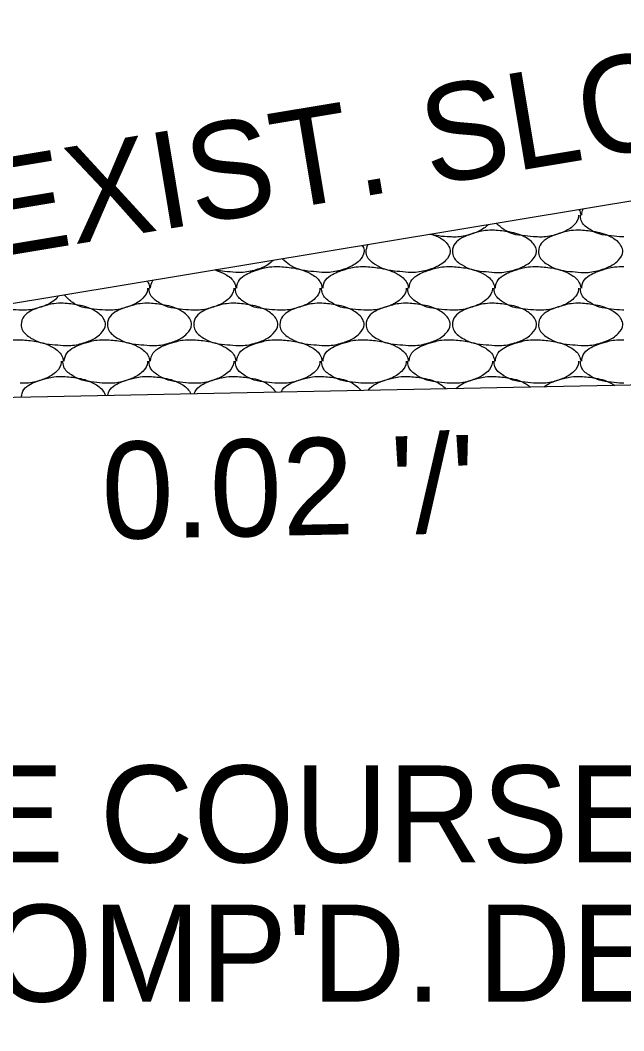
# Model space of a CAD drawing. Extents: x 1364961 to 1365294, y 367927 to 368034.
# Drawn here: x 1365179.35 to 1365182.93, y 367966.75 to 367972.75 of the extents above; entities that cross this region are included whole.
import ezdxf

# ---------------------------------------------------------------- set-up
doc = ezdxf.new("R2010")
doc.units = 0
doc.layers.add('Default', color=7, linetype='Continuous')

msp = doc.modelspace()

# ---------------------------------------------------------------- linework, layer by layer
at = {"layer": 'Default'}
for p, q in [((1365187.4981, 367972.4254), (1365166.1432, 367968.8787)), ((1365180.8861, 367971.2854), (1365180.8921, 367971.2854)), ((1365181.3981, 367971.2854), (1365181.4041, 367971.2854)), ((1365181.9101, 367971.2854), (1365181.9161, 367971.2854)), ((1365182.4221, 367971.2854), (1365182.4281, 367971.2854)), ((1365179.3501, 367970.8514), (1365179.3561, 367970.8514)), ((1365179.8621, 367970.8514), (1365179.8681, 367970.8514)), ((1365180.3741, 367970.8514), (1365180.3801, 367970.8514)), ((1365180.8861, 367970.8514), (1365180.8921, 367970.8514)), ((1365181.3981, 367970.8514), (1365181.4041, 367970.8514)), ((1365181.9101, 367970.8514), (1365181.9161, 367970.8514)), ((1365182.4221, 367970.8514), (1365182.4281, 367970.8514)), ((1365193.4821, 367970.7914), (1365175.4981, 367970.4324))]:
    msp.add_line(p, q, dxfattribs=at)
for points in [[(1365182.6701, 367971.6234), (1365182.6781, 367971.5934), (1365182.6781, 367971.5914)], [(1365182.6841, 367971.5914), (1365182.6841, 367971.5934), (1365182.6921, 367971.6274)], [(1365182.6661, 367971.5914), (1365182.6661, 367971.5854), (1365182.6381, 367971.5314), (1365182.6081, 367971.5074), (1365182.5461, 367971.4794), (1365182.4601, 367971.4614), (1365182.4221, 367971.4614)], [(1365182.9341, 367971.4614), (1365182.9261, 367971.4614), (1365182.8601, 367971.4674), (1365182.7881, 367971.4794), (1365182.7341, 367971.5054), (1365182.6841, 367971.5514), (1365182.6761, 367971.5854), (1365182.6761, 367971.5914)], [(1365182.1281, 367971.5334), (1365182.1261, 367971.5314), (1365182.0961, 367971.5074), (1365182.0341, 367971.4794), (1365181.9481, 367971.4614), (1365181.9101, 367971.4614)], [(1365182.1661, 367971.5014), (1365182.2541, 367971.4914), (1365182.3561, 367971.4554), (1365182.4081, 367971.4054), (1365182.4161, 367971.3754), (1365182.3881, 367971.3214), (1365182.3581, 367971.2974), (1365182.2961, 367971.2694), (1365182.2101, 367971.2514), (1365182.1661, 367971.2514), (1365182.1001, 367971.2574), (1365182.0281, 367971.2694), (1365181.9741, 367971.2954), (1365181.9241, 367971.3414), (1365181.9161, 367971.3754), (1365181.9321, 367971.4234), (1365181.9721, 367971.4554), (1365182.0121, 367971.4734), (1365182.0721, 367971.4914), (1365182.1101, 367971.4994), (1365182.1661, 367971.5014)], [(1365182.4221, 367971.4614), (1365182.4141, 367971.4614), (1365182.3481, 367971.4674), (1365182.2761, 367971.4794), (1365182.2221, 367971.5054), (1365182.1781, 367971.5414)], [(1365182.6781, 367971.5014), (1365182.7661, 367971.4914), (1365182.8681, 367971.4554), (1365182.9201, 367971.4054), (1365182.9281, 367971.3754), (1365182.9001, 367971.3214), (1365182.8701, 367971.2974), (1365182.8081, 367971.2694), (1365182.7221, 367971.2514), (1365182.6781, 367971.2514), (1365182.6121, 367971.2574), (1365182.5401, 367971.2694), (1365182.4861, 367971.2954), (1365182.4361, 367971.3414), (1365182.4281, 367971.3754), (1365182.4441, 367971.4234), (1365182.4841, 367971.4554), (1365182.5241, 367971.4734), (1365182.5841, 367971.4914), (1365182.6221, 367971.4994), (1365182.6781, 367971.5014)], [(1365181.7931, 367971.4774), (1365181.8441, 367971.4554), (1365181.8961, 367971.4054), (1365181.9041, 367971.3754), (1365181.8761, 367971.3214), (1365181.8461, 367971.2974), (1365181.7841, 367971.2694), (1365181.6981, 367971.2514), (1365181.6541, 367971.2514), (1365181.5881, 367971.2574), (1365181.5161, 367971.2694), (1365181.4621, 367971.2954), (1365181.4121, 367971.3414), (1365181.4041, 367971.3754), (1365181.4151, 367971.4154)], [(1365181.9101, 367971.4614), (1365181.9021, 367971.4614), (1365181.8361, 367971.4674), (1365181.7811, 367971.4754)], [(1365181.3811, 367971.4094), (1365181.3841, 367971.4054), (1365181.3921, 367971.3754), (1365181.3641, 367971.3214), (1365181.3341, 367971.2974), (1365181.2721, 367971.2694), (1365181.1861, 367971.2514), (1365181.1421, 367971.2514), (1365181.0761, 367971.2574), (1365181.0041, 367971.2694), (1365180.9501, 367971.2954), (1365180.9081, 367971.3304)], [(1365180.8521, 367971.3214), (1365180.8221, 367971.2974), (1365180.7601, 367971.2694), (1365180.6741, 367971.2514), (1365180.6301, 367971.2514), (1365180.5641, 367971.2574), (1365180.5121, 367971.2654)], [(1365180.5101, 367971.2644), (1365180.5701, 367971.2394), (1365180.6221, 367971.1894), (1365180.6301, 367971.1594), (1365180.6301, 367971.1574)], [(1365180.6361, 367971.1574), (1365180.6361, 367971.1594), (1365180.6521, 367971.2074), (1365180.6921, 367971.2394), (1365180.7321, 367971.2574), (1365180.7921, 367971.2754), (1365180.8301, 367971.2834), (1365180.8861, 367971.2854)], [(1365180.8921, 367971.2854), (1365180.9801, 367971.2754), (1365181.0821, 367971.2394), (1365181.1341, 367971.1894), (1365181.1421, 367971.1594), (1365181.1421, 367971.1574)], [(1365181.1481, 367971.1574), (1365181.1481, 367971.1594), (1365181.1641, 367971.2074), (1365181.2041, 367971.2394), (1365181.2441, 367971.2574), (1365181.3041, 367971.2754), (1365181.3421, 367971.2834), (1365181.3981, 367971.2854)], [(1365181.4041, 367971.2854), (1365181.4921, 367971.2754), (1365181.5941, 367971.2394), (1365181.6461, 367971.1894), (1365181.6541, 367971.1594), (1365181.6541, 367971.1574)], [(1365181.6601, 367971.1574), (1365181.6601, 367971.1594), (1365181.6761, 367971.2074), (1365181.7161, 367971.2394), (1365181.7561, 367971.2574), (1365181.8161, 367971.2754), (1365181.8541, 367971.2834), (1365181.9101, 367971.2854)], [(1365181.9161, 367971.2854), (1365182.0041, 367971.2754), (1365182.1061, 367971.2394), (1365182.1581, 367971.1894), (1365182.1661, 367971.1594), (1365182.1661, 367971.1574)], [(1365182.1721, 367971.1574), (1365182.1721, 367971.1594), (1365182.1881, 367971.2074), (1365182.2281, 367971.2394), (1365182.2681, 367971.2574), (1365182.3281, 367971.2754), (1365182.3661, 367971.2834), (1365182.4221, 367971.2854)], [(1365182.4281, 367971.2854), (1365182.5161, 367971.2754), (1365182.6181, 367971.2394), (1365182.6701, 367971.1894), (1365182.6781, 367971.1594), (1365182.6781, 367971.1574)], [(1365182.6841, 367971.1574), (1365182.6841, 367971.1594), (1365182.7001, 367971.2074), (1365182.7401, 367971.2394), (1365182.7801, 367971.2574), (1365182.8401, 367971.2754), (1365182.8781, 367971.2834), (1365182.9341, 367971.2854)], [(1365180.1051, 367971.1974), (1365180.1101, 367971.1894), (1365180.1181, 367971.1594), (1365180.1181, 367971.1574)], [(1365180.1241, 367971.1574), (1365180.1241, 367971.1594), (1365180.1371, 367971.2024)], [(1365180.1061, 367971.1574), (1365180.1061, 367971.1514), (1365180.0781, 367971.0974), (1365180.0481, 367971.0734), (1365179.9861, 367971.0454), (1365179.9001, 367971.0274), (1365179.8621, 367971.0274)], [(1365180.3741, 367971.0274), (1365180.3661, 367971.0274), (1365180.3001, 367971.0334), (1365180.2281, 367971.0454), (1365180.1741, 367971.0714), (1365180.1241, 367971.1174), (1365180.1161, 367971.1514), (1365180.1161, 367971.1574)], [(1365180.6181, 367971.1574), (1365180.6181, 367971.1514), (1365180.5901, 367971.0974), (1365180.5601, 367971.0734), (1365180.4981, 367971.0454), (1365180.4121, 367971.0274), (1365180.3741, 367971.0274)], [(1365180.8861, 367971.0274), (1365180.8781, 367971.0274), (1365180.8121, 367971.0334), (1365180.7401, 367971.0454), (1365180.6861, 367971.0714), (1365180.6361, 367971.1174), (1365180.6281, 367971.1514), (1365180.6281, 367971.1574)], [(1365181.1301, 367971.1574), (1365181.1301, 367971.1514), (1365181.1021, 367971.0974), (1365181.0721, 367971.0734), (1365181.0101, 367971.0454), (1365180.9241, 367971.0274), (1365180.8861, 367971.0274)], [(1365181.3981, 367971.0274), (1365181.3901, 367971.0274), (1365181.3241, 367971.0334), (1365181.2521, 367971.0454), (1365181.1981, 367971.0714), (1365181.1481, 367971.1174), (1365181.1401, 367971.1514), (1365181.1401, 367971.1574)], [(1365181.6421, 367971.1574), (1365181.6421, 367971.1514), (1365181.6141, 367971.0974), (1365181.5841, 367971.0734), (1365181.5221, 367971.0454), (1365181.4361, 367971.0274), (1365181.3981, 367971.0274)], [(1365181.9101, 367971.0274), (1365181.9021, 367971.0274), (1365181.8361, 367971.0334), (1365181.7641, 367971.0454), (1365181.7101, 367971.0714), (1365181.6601, 367971.1174), (1365181.6521, 367971.1514), (1365181.6521, 367971.1574)], [(1365182.1541, 367971.1574), (1365182.1541, 367971.1514), (1365182.1261, 367971.0974), (1365182.0961, 367971.0734), (1365182.0341, 367971.0454), (1365181.9481, 367971.0274), (1365181.9101, 367971.0274)], [(1365182.4221, 367971.0274), (1365182.4141, 367971.0274), (1365182.3481, 367971.0334), (1365182.2761, 367971.0454), (1365182.2221, 367971.0714), (1365182.1721, 367971.1174), (1365182.1641, 367971.1514), (1365182.1641, 367971.1574)], [(1365182.6661, 367971.1574), (1365182.6661, 367971.1514), (1365182.6381, 367971.0974), (1365182.6081, 367971.0734), (1365182.5461, 367971.0454), (1365182.4601, 367971.0274), (1365182.4221, 367971.0274)], [(1365182.9341, 367971.0274), (1365182.9261, 367971.0274), (1365182.8601, 367971.0334), (1365182.7881, 367971.0454), (1365182.7341, 367971.0714), (1365182.6841, 367971.1174), (1365182.6761, 367971.1514), (1365182.6761, 367971.1574)], [(1365179.5761, 367971.1094), (1365179.5661, 367971.0974), (1365179.5361, 367971.0734), (1365179.4741, 367971.0454), (1365179.3881, 367971.0274), (1365179.3501, 367971.0274)], [(1365179.6061, 367971.0674), (1365179.6941, 367971.0574), (1365179.7961, 367971.0214), (1365179.8481, 367970.9714), (1365179.8561, 367970.9414), (1365179.8281, 367970.8874), (1365179.7981, 367970.8634), (1365179.7361, 367970.8354), (1365179.6501, 367970.8174), (1365179.6061, 367970.8174), (1365179.5401, 367970.8234), (1365179.4681, 367970.8354), (1365179.4141, 367970.8614), (1365179.3641, 367970.9074), (1365179.3561, 367970.9414), (1365179.3721, 367970.9894), (1365179.4121, 367971.0214), (1365179.4521, 367971.0394), (1365179.5121, 367971.0574), (1365179.5501, 367971.0654), (1365179.6061, 367971.0674)], [(1365179.8621, 367971.0274), (1365179.8541, 367971.0274), (1365179.7881, 367971.0334), (1365179.7161, 367971.0454), (1365179.6621, 367971.0714), (1365179.6131, 367971.1154)], [(1365180.1181, 367971.0674), (1365180.2061, 367971.0574), (1365180.3081, 367971.0214), (1365180.3601, 367970.9714), (1365180.3681, 367970.9414), (1365180.3401, 367970.8874), (1365180.3101, 367970.8634), (1365180.2481, 367970.8354), (1365180.1621, 367970.8174), (1365180.1181, 367970.8174), (1365180.0521, 367970.8234), (1365179.9801, 367970.8354), (1365179.9261, 367970.8614), (1365179.8761, 367970.9074), (1365179.8681, 367970.9414), (1365179.8841, 367970.9894), (1365179.9241, 367971.0214), (1365179.9641, 367971.0394), (1365180.0241, 367971.0574), (1365180.0621, 367971.0654), (1365180.1181, 367971.0674)], [(1365180.6301, 367971.0674), (1365180.7181, 367971.0574), (1365180.8201, 367971.0214), (1365180.8721, 367970.9714), (1365180.8801, 367970.9414), (1365180.8521, 367970.8874), (1365180.8221, 367970.8634), (1365180.7601, 367970.8354), (1365180.6741, 367970.8174), (1365180.6301, 367970.8174), (1365180.5641, 367970.8234), (1365180.4921, 367970.8354), (1365180.4381, 367970.8614), (1365180.3881, 367970.9074), (1365180.3801, 367970.9414), (1365180.3961, 367970.9894), (1365180.4361, 367971.0214), (1365180.4761, 367971.0394), (1365180.5361, 367971.0574), (1365180.5741, 367971.0654), (1365180.6301, 367971.0674)], [(1365181.1421, 367971.0674), (1365181.2301, 367971.0574), (1365181.3321, 367971.0214), (1365181.3841, 367970.9714), (1365181.3921, 367970.9414), (1365181.3641, 367970.8874), (1365181.3341, 367970.8634), (1365181.2721, 367970.8354), (1365181.1861, 367970.8174), (1365181.1421, 367970.8174), (1365181.0761, 367970.8234), (1365181.0041, 367970.8354), (1365180.9501, 367970.8614), (1365180.9001, 367970.9074), (1365180.8921, 367970.9414), (1365180.9081, 367970.9894), (1365180.9481, 367971.0214), (1365180.9881, 367971.0394), (1365181.0481, 367971.0574), (1365181.0861, 367971.0654), (1365181.1421, 367971.0674)], [(1365181.6541, 367971.0674), (1365181.7421, 367971.0574), (1365181.8441, 367971.0214), (1365181.8961, 367970.9714), (1365181.9041, 367970.9414), (1365181.8761, 367970.8874), (1365181.8461, 367970.8634), (1365181.7841, 367970.8354), (1365181.6981, 367970.8174), (1365181.6541, 367970.8174), (1365181.5881, 367970.8234), (1365181.5161, 367970.8354), (1365181.4621, 367970.8614), (1365181.4121, 367970.9074), (1365181.4041, 367970.9414), (1365181.4201, 367970.9894), (1365181.4601, 367971.0214), (1365181.5001, 367971.0394), (1365181.5601, 367971.0574), (1365181.5981, 367971.0654), (1365181.6541, 367971.0674)], [(1365182.1661, 367971.0674), (1365182.2541, 367971.0574), (1365182.3561, 367971.0214), (1365182.4081, 367970.9714), (1365182.4161, 367970.9414), (1365182.3881, 367970.8874), (1365182.3581, 367970.8634), (1365182.2961, 367970.8354), (1365182.2101, 367970.8174), (1365182.1661, 367970.8174), (1365182.1001, 367970.8234), (1365182.0281, 367970.8354), (1365181.9741, 367970.8614), (1365181.9241, 367970.9074), (1365181.9161, 367970.9414), (1365181.9321, 367970.9894), (1365181.9721, 367971.0214), (1365182.0121, 367971.0394), (1365182.0721, 367971.0574), (1365182.1101, 367971.0654), (1365182.1661, 367971.0674)], [(1365182.6781, 367971.0674), (1365182.7661, 367971.0574), (1365182.8681, 367971.0214), (1365182.9201, 367970.9714), (1365182.9281, 367970.9414), (1365182.9001, 367970.8874), (1365182.8701, 367970.8634), (1365182.8081, 367970.8354), (1365182.7221, 367970.8174), (1365182.6781, 367970.8174), (1365182.6121, 367970.8234), (1365182.5401, 367970.8354), (1365182.4861, 367970.8614), (1365182.4361, 367970.9074), (1365182.4281, 367970.9414), (1365182.4441, 367970.9894), (1365182.4841, 367971.0214), (1365182.5241, 367971.0394), (1365182.5841, 367971.0574), (1365182.6221, 367971.0654), (1365182.6781, 367971.0674)], [(1365179.3501, 367971.0274), (1365179.3421, 367971.0274), (1365179.2761, 367971.0334), (1365179.2041, 367971.0454), (1365179.1981, 367971.0474)], [(1365179.1001, 367970.7234), (1365179.1001, 367970.7254), (1365179.1161, 367970.7734), (1365179.1561, 367970.8054), (1365179.1961, 367970.8234), (1365179.2561, 367970.8414), (1365179.2941, 367970.8494), (1365179.3501, 367970.8514)], [(1365179.3561, 367970.8514), (1365179.4441, 367970.8414), (1365179.5461, 367970.8054), (1365179.5981, 367970.7554), (1365179.6061, 367970.7254), (1365179.6061, 367970.7234)], [(1365179.6121, 367970.7234), (1365179.6121, 367970.7254), (1365179.6281, 367970.7734), (1365179.6681, 367970.8054), (1365179.7081, 367970.8234), (1365179.7681, 367970.8414), (1365179.8061, 367970.8494), (1365179.8621, 367970.8514)], [(1365179.8681, 367970.8514), (1365179.9561, 367970.8414), (1365180.0581, 367970.8054), (1365180.1101, 367970.7554), (1365180.1181, 367970.7254), (1365180.1181, 367970.7234)], [(1365180.1241, 367970.7234), (1365180.1241, 367970.7254), (1365180.1401, 367970.7734), (1365180.1801, 367970.8054), (1365180.2201, 367970.8234), (1365180.2801, 367970.8414), (1365180.3181, 367970.8494), (1365180.3741, 367970.8514)], [(1365180.3801, 367970.8514), (1365180.4681, 367970.8414), (1365180.5701, 367970.8054), (1365180.6221, 367970.7554), (1365180.6301, 367970.7254), (1365180.6301, 367970.7234)], [(1365180.6361, 367970.7234), (1365180.6361, 367970.7254), (1365180.6521, 367970.7734), (1365180.6921, 367970.8054), (1365180.7321, 367970.8234), (1365180.7921, 367970.8414), (1365180.8301, 367970.8494), (1365180.8861, 367970.8514)], [(1365180.8921, 367970.8514), (1365180.9801, 367970.8414), (1365181.0821, 367970.8054), (1365181.1341, 367970.7554), (1365181.1421, 367970.7254), (1365181.1421, 367970.7234)], [(1365181.1481, 367970.7234), (1365181.1481, 367970.7254), (1365181.1641, 367970.7734), (1365181.2041, 367970.8054), (1365181.2441, 367970.8234), (1365181.3041, 367970.8414), (1365181.3421, 367970.8494), (1365181.3981, 367970.8514)], [(1365181.4041, 367970.8514), (1365181.4921, 367970.8414), (1365181.5941, 367970.8054), (1365181.6461, 367970.7554), (1365181.6541, 367970.7254), (1365181.6541, 367970.7234)], [(1365181.6601, 367970.7234), (1365181.6601, 367970.7254), (1365181.6761, 367970.7734), (1365181.7161, 367970.8054), (1365181.7561, 367970.8234), (1365181.8161, 367970.8414), (1365181.8541, 367970.8494), (1365181.9101, 367970.8514)], [(1365181.9161, 367970.8514), (1365182.0041, 367970.8414), (1365182.1061, 367970.8054), (1365182.1581, 367970.7554), (1365182.1661, 367970.7254), (1365182.1661, 367970.7234)], [(1365182.1721, 367970.7234), (1365182.1721, 367970.7254), (1365182.1881, 367970.7734), (1365182.2281, 367970.8054), (1365182.2681, 367970.8234), (1365182.3281, 367970.8414), (1365182.3661, 367970.8494), (1365182.4221, 367970.8514)], [(1365182.4281, 367970.8514), (1365182.5161, 367970.8414), (1365182.6181, 367970.8054), (1365182.6701, 367970.7554), (1365182.6781, 367970.7254), (1365182.6781, 367970.7234)], [(1365182.6841, 367970.7234), (1365182.6841, 367970.7254), (1365182.7001, 367970.7734), (1365182.7401, 367970.8054), (1365182.7801, 367970.8234), (1365182.8401, 367970.8414), (1365182.8781, 367970.8494), (1365182.9341, 367970.8514)], [(1365179.5941, 367970.7234), (1365179.5941, 367970.7174), (1365179.5661, 367970.6634), (1365179.5361, 367970.6394), (1365179.4741, 367970.6114), (1365179.3881, 367970.5934), (1365179.3501, 367970.5934)], [(1365179.8621, 367970.5934), (1365179.8541, 367970.5934), (1365179.7881, 367970.5994), (1365179.7161, 367970.6114), (1365179.6621, 367970.6374), (1365179.6121, 367970.6834), (1365179.6041, 367970.7174), (1365179.6041, 367970.7234)], [(1365180.1061, 367970.7234), (1365180.1061, 367970.7174), (1365180.0781, 367970.6634), (1365180.0481, 367970.6394), (1365179.9861, 367970.6114), (1365179.9001, 367970.5934), (1365179.8621, 367970.5934)], [(1365180.3741, 367970.5934), (1365180.3661, 367970.5934), (1365180.3001, 367970.5994), (1365180.2281, 367970.6114), (1365180.1741, 367970.6374), (1365180.1241, 367970.6834), (1365180.1161, 367970.7174), (1365180.1161, 367970.7234)], [(1365180.6181, 367970.7234), (1365180.6181, 367970.7174), (1365180.5901, 367970.6634), (1365180.5601, 367970.6394), (1365180.4981, 367970.6114), (1365180.4121, 367970.5934), (1365180.3741, 367970.5934)], [(1365180.8861, 367970.5934), (1365180.8781, 367970.5934), (1365180.8121, 367970.5994), (1365180.7401, 367970.6114), (1365180.6861, 367970.6374), (1365180.6361, 367970.6834), (1365180.6281, 367970.7174), (1365180.6281, 367970.7234)], [(1365181.1301, 367970.7234), (1365181.1301, 367970.7174), (1365181.1021, 367970.6634), (1365181.0721, 367970.6394), (1365181.0101, 367970.6114), (1365180.9241, 367970.5934), (1365180.8861, 367970.5934)], [(1365181.3981, 367970.5934), (1365181.3901, 367970.5934), (1365181.3241, 367970.5994), (1365181.2521, 367970.6114), (1365181.1981, 367970.6374), (1365181.1481, 367970.6834), (1365181.1401, 367970.7174), (1365181.1401, 367970.7234)], [(1365181.6421, 367970.7234), (1365181.6421, 367970.7174), (1365181.6141, 367970.6634), (1365181.5841, 367970.6394), (1365181.5221, 367970.6114), (1365181.4361, 367970.5934), (1365181.3981, 367970.5934)], [(1365181.9101, 367970.5934), (1365181.9021, 367970.5934), (1365181.8361, 367970.5994), (1365181.7641, 367970.6114), (1365181.7101, 367970.6374), (1365181.6601, 367970.6834), (1365181.6521, 367970.7174), (1365181.6521, 367970.7234)], [(1365182.1541, 367970.7234), (1365182.1541, 367970.7174), (1365182.1261, 367970.6634), (1365182.0961, 367970.6394), (1365182.0341, 367970.6114), (1365181.9481, 367970.5934), (1365181.9101, 367970.5934)], [(1365182.4221, 367970.5934), (1365182.4141, 367970.5934), (1365182.3481, 367970.5994), (1365182.2761, 367970.6114), (1365182.2221, 367970.6374), (1365182.1721, 367970.6834), (1365182.1641, 367970.7174), (1365182.1641, 367970.7234)], [(1365182.6661, 367970.7234), (1365182.6661, 367970.7174), (1365182.6381, 367970.6634), (1365182.6081, 367970.6394), (1365182.5461, 367970.6114), (1365182.4601, 367970.5934), (1365182.4221, 367970.5934)], [(1365182.9341, 367970.5934), (1365182.9261, 367970.5934), (1365182.8601, 367970.5994), (1365182.7881, 367970.6114), (1365182.7341, 367970.6374), (1365182.6841, 367970.6834), (1365182.6761, 367970.7174), (1365182.6761, 367970.7234)], [(1365179.3561, 367970.5094), (1365179.3721, 367970.5554), (1365179.4121, 367970.5874), (1365179.4521, 367970.6054), (1365179.5121, 367970.6234), (1365179.5501, 367970.6314), (1365179.6061, 367970.6334)], [(1365179.6061, 367970.6334), (1365179.6941, 367970.6234), (1365179.7961, 367970.5874), (1365179.8481, 367970.5374), (1365179.8561, 367970.5194)], [(1365179.8691, 367970.5194), (1365179.8841, 367970.5554), (1365179.9241, 367970.5874), (1365179.9641, 367970.6054), (1365180.0241, 367970.6234), (1365180.0621, 367970.6314), (1365180.1181, 367970.6334)], [(1365180.1181, 367970.6334), (1365180.2061, 367970.6234), (1365180.3081, 367970.5874), (1365180.3601, 367970.5374), (1365180.3641, 367970.5294)], [(1365180.3831, 367970.5304), (1365180.3961, 367970.5554), (1365180.4361, 367970.5874), (1365180.4761, 367970.6054), (1365180.5361, 367970.6234), (1365180.5741, 367970.6314), (1365180.6301, 367970.6334)], [(1365180.6301, 367970.6334), (1365180.7181, 367970.6234), (1365180.8201, 367970.5874), (1365180.8701, 367970.5394)], [(1365180.8991, 367970.5404), (1365180.9081, 367970.5554), (1365180.9481, 367970.5874), (1365180.9881, 367970.6054), (1365181.0481, 367970.6234), (1365181.0861, 367970.6314), (1365181.1421, 367970.6334)], [(1365181.1421, 367970.6334), (1365181.2301, 367970.6234), (1365181.3321, 367970.5874), (1365181.3751, 367970.5494)], [(1365181.4171, 367970.5504), (1365181.4201, 367970.5554), (1365181.4601, 367970.5874), (1365181.5001, 367970.6054), (1365181.5601, 367970.6234), (1365181.5981, 367970.6314), (1365181.6541, 367970.6334)], [(1365181.6541, 367970.6334), (1365181.7421, 367970.6234), (1365181.8441, 367970.5874), (1365181.8791, 367970.5594)], [(1365181.9361, 367970.5614), (1365181.9721, 367970.5874), (1365182.0121, 367970.6054), (1365182.0721, 367970.6234), (1365182.1101, 367970.6314), (1365182.1661, 367970.6334)], [(1365182.1661, 367970.6334), (1365182.2541, 367970.6234), (1365182.3561, 367970.5874), (1365182.3811, 367970.5694)], [(1365182.4591, 367970.5714), (1365182.4841, 367970.5874), (1365182.5241, 367970.6054), (1365182.5841, 367970.6234), (1365182.6221, 367970.6314), (1365182.6781, 367970.6334)], [(1365182.6781, 367970.6334), (1365182.7661, 367970.6234), (1365182.8681, 367970.5874), (1365182.8801, 367970.5794)]]:
    msp.add_spline(points, degree=3, dxfattribs=at)

# ---------------------------------------------------------------- texts
for s, rotation, p in [('EXIST. SLOPE', 9.4298, (1365179.1632, 367971.3326)), ("0.02 '/'", 1.14267, (1365179.8387, 367969.6668))]:
    msp.add_text(s, height=0.576, rotation=rotation, dxfattribs=at).set_placement(p)
for s, p in [('AGGREGATE BASE COURSE', (1365172.4606, 367967.7471)), ("(CLASS 7)- VAR. COMP'D. DEPTH", (1365172.4606, 367966.9211))]:
    msp.add_text(s, height=0.576, dxfattribs=at).set_placement(p)

doc.saveas('drawing.dxf')
